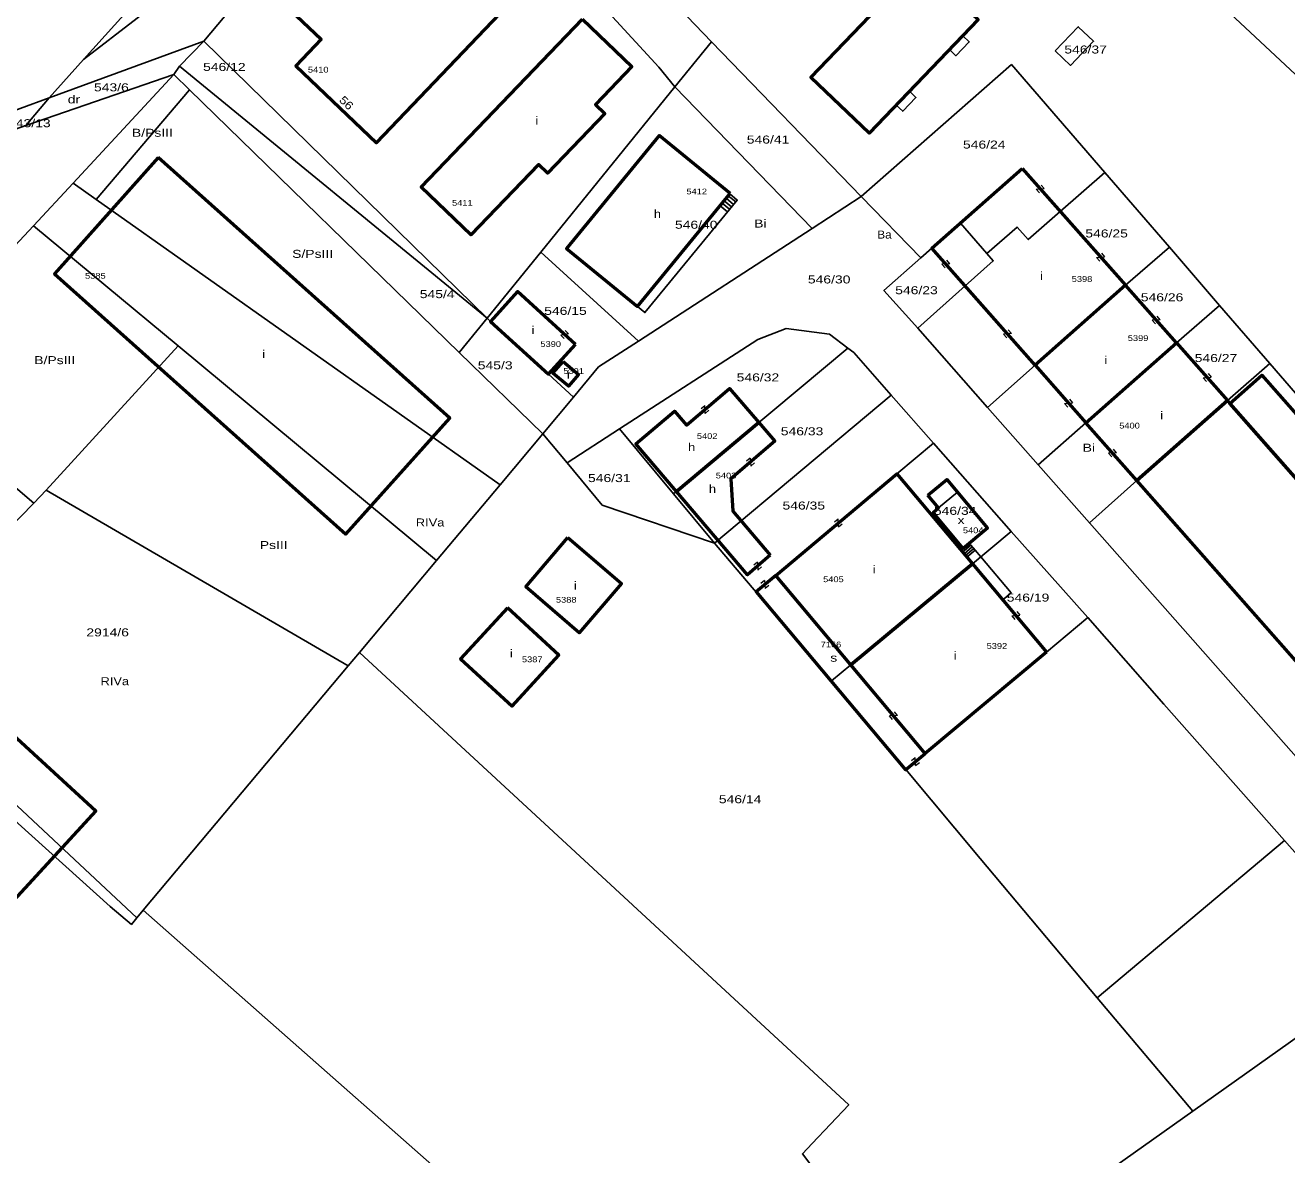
# Model space of a CAD drawing. Extents: x 4641351 to 4644672, y 5357112 to 5362385.
# Drawn here: x 4642962.5 to 4643159.5, y 5360710 to 5360886.4 of the extents above; entities that cross this region are included whole.
import ezdxf
from ezdxf.enums import TextEntityAlignment as Align

# ---------------------------------------------------------------- set-up
doc = ezdxf.new("R2010")
doc.units = 0
doc.header["$LTSCALE"] = 0.5
for name, color, linetype in [('1', 7, 'Continuous'), ('24', 7, 'Continuous'), ('26', 7, 'Continuous'), ('4', 7, 'Continuous')]:
    doc.layers.add(name, color=color, linetype=linetype)
for name, color, linetype, lineweight in [('15', 7, 'Continuous', 25), ('16', 7, 'Continuous', 25), ('25', 7, 'Continuous', 25), ('27', 7, 'Continuous', 25), ('3', 7, 'Continuous', 13), ('6', 7, 'Continuous', 25)]:
    doc.layers.add(name, color=color, linetype=linetype, lineweight=lineweight)

msp = doc.modelspace()

# ---------------------------------------------------------------- linework, layer by layer
at = {"layer": '15'}
for p, q in [((4643072.817, 5360858.076), (4643071.657, 5360859.028)), ((4643073.134, 5360858.463), (4643071.974, 5360859.415)), ((4643073.451, 5360858.849), (4643072.291, 5360859.801)), ((4643072.183, 5360857.303), (4643071.023, 5360858.255)), ((4643072.5, 5360857.69), (4643071.34, 5360858.642)), ((4643110.632, 5360804.726), (4643109.335, 5360803.637))]:
    msp.add_line(p, q, dxfattribs=at)
for points in [[(4643058.105, 5360842.516), (4643059.265, 5360841.564), (4643073.69, 5360859.14), (4643072.53, 5360860.092)], [(4643109.555, 5360803.376), (4643110.851, 5360804.465), (4643110.191, 5360805.251), (4643108.894, 5360804.162)], [(4643110.421, 5360802.344), (4643111.718, 5360803.433), (4643110.852, 5360804.465), (4643109.555, 5360803.376)], [(4643110.421, 5360802.344), (4643111.718, 5360803.433), (4643116.455, 5360797.792), (4643115.158, 5360796.703)]]:
    msp.add_lwpolyline(points, close=True, dxfattribs=at)
msp.add_lwpolyline([(4643110.411, 5360804.989), (4643110.412, 5360804.989), (4643109.115, 5360803.899)], dxfattribs=at)
at = {"layer": '16'}
for points in [[(4643108.909, 5360884.807), (4643109.919, 5360883.838), (4643107.842, 5360881.673), (4643106.832, 5360882.642)], [(4643100.601, 5360876.148), (4643101.611, 5360875.179), (4643099.534, 5360873.014), (4643098.524, 5360873.983)]]:
    msp.add_lwpolyline(points, close=True, dxfattribs=at)
at = {"layer": '25'}
for p, q in [((4643034.618, 5360840.702), (4642990.368, 5360883.956)), ((4642962.597, 5360870.762), (4642966.205, 5360875.094)), ((4643063.761, 5360813.259), (4643090.967, 5360836.02)), ((4643070.16, 5360805.568), (4643097.742, 5360828.664)), ((4643116.466, 5360807.362), (4643110.421, 5360802.344))]:
    msp.add_line(p, q, dxfattribs=at)
for points in [[(4643069.651, 5360883.835), (4643093.07, 5360859.707), (4643116.529, 5360880.298), (4643131.101, 5360863.442), (4643141.186, 5360851.776), (4643149.036, 5360842.696), (4643156.868, 5360833.637), (4643184.618, 5360801.537), (4643214.585, 5360827.069), (4643236.635, 5360845.843), (4643221.786, 5360867.068), (4643195.021, 5360847.847), (4643169.275, 5360871.091), (4643163.235, 5360876.545), (4643124.137, 5360913.093), (4643100.704, 5360935.255)], [(4643063.945, 5360876.814), (4643069.651, 5360883.835), (4643059.534, 5360894.45), (4643037.963, 5360917.65), (4643027.414, 5360926.568)], [(4643034.618, 5360840.702), (4643043.005, 5360850.99), (4643063.945, 5360876.814), (4643061.441, 5360879.907), (4643045.808, 5360896.938), (4643031.568, 5360910.853), (4643023.758, 5360919.579), (4643022.322, 5360920.713), (4643011.407, 5360909.06)], [(4642961.719, 5360873.449), (4642966.205, 5360875.094), (4642971.614, 5360881.095), (4643003.059, 5360915.975), (4642999.77, 5360918.699), (4642994.247, 5360913.207), (4642984.526, 5360904.064), (4642964.268, 5360890.656), (4642955.311, 5360884.878), (4642930.858, 5360865.649), (4642926.797, 5360863.336), (4642922.443, 5360859.045)], [(4642990.368, 5360883.956), (4643011.407, 5360909.06), (4643008.564, 5360911.382), (4642996.718, 5360900.487), (4642971.614, 5360881.095)], [(4642985.672, 5360878.737), (4642986.592, 5360880.024), (4642990.368, 5360883.956), (4642966.205, 5360875.094)], [(4642938.39, 5360782.43), (4642958.734, 5360764.143), (4642975.77, 5360748.826), (4642979.077, 5360746.004), (4642979.936, 5360747.03), (4642980.927, 5360748.211), (4643012.937, 5360786.377), (4643014.684, 5360788.461), (4643026.742, 5360802.84), (4643036.653, 5360814.656), (4643043.329, 5360822.616), (4643030.257, 5360835.336), (4642988.127, 5360876.348), (4642985.672, 5360878.737), (4642962.597, 5360870.762), (4642955.59, 5360868.34)], [(4643030.257, 5360835.336), (4643034.618, 5360840.702), (4642986.592, 5360880.024)], [(4643058.255, 5360837.085), (4643085.39, 5360854.71), (4643063.945, 5360876.814)], [(4643102.381, 5360850.115), (4643104.096, 5360851.629), (4643108.549, 5360855.545), (4643112.686, 5360850.769), (4643117.404, 5360854.928), (4643119.153, 5360852.966), (4643124.131, 5360857.366), (4643131.101, 5360863.442)], [(4643266.424, 5360802.366), (4643263.866, 5360805.827), (4643261.783, 5360808.646), (4643211.704, 5360773.753), (4643179.474, 5360751.053), (4643160.966, 5360772.173), (4643128.7, 5360808.727), (4643120.697, 5360817.766), (4643112.778, 5360826.718), (4643101.889, 5360839.154), (4643096.614, 5360845.019), (4643102.381, 5360850.115), (4643093.07, 5360859.707), (4643085.39, 5360854.71)], [(4643048.115, 5360828.339), (4643052.03, 5360833.076), (4643058.255, 5360837.085), (4643043.005, 5360850.99)], [(4643112.778, 5360826.718), (4643120.209, 5360833.366), (4643134.344, 5360845.823), (4643141.186, 5360851.776)], [(4643101.889, 5360839.154), (4643109.272, 5360845.76), (4643113.681, 5360849.637), (4643112.686, 5360850.769)], [(4643120.697, 5360817.766), (4643128.14, 5360824.365), (4643142.316, 5360836.823), (4643149.036, 5360842.696)], [(4643043.329, 5360822.616), (4643048.115, 5360828.339), (4643044.22, 5360831.937), (4643035.158, 5360840.193), (4643034.618, 5360840.702)], [(4643047.11, 5360818.093), (4643055.325, 5360823.391), (4643076.936, 5360837.335), (4643081.35, 5360839.071), (4643088.079, 5360838.197), (4643090.967, 5360836.02), (4643091.885, 5360835.326), (4643097.742, 5360828.664), (4643104.333, 5360821.16), (4643116.466, 5360807.362), (4643128.426, 5360793.918), (4643140.298, 5360780.41), (4643159.153, 5360759.103), (4643176.605, 5360739.362)], [(4643128.7, 5360808.727), (4643136.081, 5360815.364), (4643150.266, 5360827.843), (4643156.868, 5360833.637)], [(4643070.16, 5360805.568), (4643063.761, 5360813.259), (4643055.325, 5360823.391)], [(4643144.866, 5360716.862), (4643129.888, 5360734.54), (4643111.615, 5360756.3), (4643100.008, 5360770.188), (4643088.402, 5360784.067), (4643070.16, 5360805.568), (4643052.614, 5360811.507), (4643047.11, 5360818.093), (4643043.329, 5360822.616)], [(4643088.402, 5360784.067), (4643091.416, 5360786.569), (4643110.421, 5360802.344), (4643098.619, 5360816.381), (4643104.333, 5360821.16)], [(4643266.424, 5360802.366), (4643241.486, 5360784.406), (4643211.598, 5360763.109), (4643176.605, 5360739.362), (4643144.866, 5360716.862), (4643103.076, 5360687.21), (4643043.425, 5360643.495), (4642978.815, 5360596.146), (4642952.32, 5360560.117), (4642913.168, 5360505.182), (4642909.005, 5360494.861), (4642897.054, 5360474.757), (4642897.62, 5360474.44), (4642886.991, 5360460.422)], [(4643100.008, 5360770.188), (4643103.043, 5360772.722), (4643122.002, 5360788.553), (4643128.426, 5360793.918)], [(4643014.684, 5360788.461), (4643091.115, 5360717.855), (4643085.385, 5360711.775), (4643083.869, 5360710.166), (4643093.53, 5360697.488), (4643094.895, 5360698.515), (4643103.076, 5360687.21)]]:
    msp.add_lwpolyline(points, dxfattribs=at)
msp.add_lwpolyline([(4643123.339, 5360882.419), (4643125.76, 5360880.164), (4643129.362, 5360883.939), (4643126.962, 5360886.195)], close=True, dxfattribs=at)
at = {"layer": '27'}
for points in [[(4642966.205, 5360875.094), (4642971.614, 5360881.095), (4642996.718, 5360900.487), (4643008.564, 5360911.382), (4643022.156, 5360923.888), (4643059.701, 5360971.966), (4643061.134, 5360973.801), (4643117.007, 5361026.845), (4643161.963, 5361072.833), (4643185.093, 5361090.619), (4643211.568, 5361122.216), (4643225.268, 5361138.578), (4643232.759, 5361147.52), (4643257.532, 5361174.087)], [(4643266.424, 5360802.366), (4643263.866, 5360805.827), (4643261.783, 5360808.646), (4643312.049, 5360844.358), (4643348.449, 5360870.219), (4643347.38, 5360871.06), (4643328.35, 5360886.006), (4643322.35, 5360889.651), (4643295.026, 5360869.061), (4643271.24, 5360903.578), (4643227.458, 5360871.385), (4643221.786, 5360867.068), (4643195.021, 5360847.847), (4643169.275, 5360871.091), (4643163.235, 5360876.545), (4643124.137, 5360913.093), (4643100.704, 5360935.255), (4643074.641, 5360909.408), (4643059.534, 5360894.45), (4643037.963, 5360917.65), (4643027.414, 5360926.568), (4643022.322, 5360920.713), (4643011.407, 5360909.06)], [(4642990.368, 5360883.956), (4643011.407, 5360909.06), (4643008.564, 5360911.382)], [(4643404.058, 5360902.512), (4643353.914, 5360865.927), (4643316.19, 5360838.578), (4643266.424, 5360802.366), (4643241.486, 5360784.406), (4643211.598, 5360763.109), (4643176.605, 5360739.362), (4643144.866, 5360716.862), (4643103.076, 5360687.21)], [(4642954.708, 5360868.034), (4642955.59, 5360868.34), (4642962.597, 5360870.762), (4642985.672, 5360878.737), (4642986.592, 5360880.024), (4642990.368, 5360883.956), (4642966.205, 5360875.094), (4642961.719, 5360873.449), (4642922.443, 5360859.045), (4642913.439, 5360855.743), (4642908.738, 5360853.709), (4642885.535, 5360844.16), (4642866.506, 5360838.934), (4642864.482, 5360838.514)], [(4642934.508, 5360821.537), (4642935.707, 5360823.178), (4642950.956, 5360840.529), (4642958.74, 5360849.687), (4642963.785, 5360855.129), (4642969.95, 5360861.779), (4642985.672, 5360878.737)], [(4642973.575, 5360859.218), (4642988.127, 5360876.348), (4642985.672, 5360878.737)], [(4643036.653, 5360814.656), (4643043.329, 5360822.616), (4643048.115, 5360828.339), (4643044.22, 5360831.937), (4643035.158, 5360840.193), (4643034.618, 5360840.702), (4642986.592, 5360880.024)], [(4642986.394, 5360836.351), (4643026.742, 5360802.84), (4643036.653, 5360814.656), (4642973.575, 5360859.218), (4642969.95, 5360861.779)], [(4642963.816, 5360811.825), (4642965.756, 5360813.808), (4642986.394, 5360836.351), (4642963.785, 5360855.129)], [(4642864.42, 5360741.249), (4642904.695, 5360730.14), (4642905.897, 5360734.858), (4642909.222, 5360743.582), (4642913.126, 5360751.433), (4642918.085, 5360758.796), (4642921.09, 5360764.54), (4642924.397, 5360770.846), (4642935.125, 5360788.291), (4642938.4, 5360785.837), (4642963.816, 5360811.825), (4642951.631, 5360822.167), (4642943.532, 5360813.297), (4642934.508, 5360821.537), (4642929.655, 5360814.892), (4642921.095, 5360803.173), (4642915.206, 5360790.475), (4642892.458, 5360790.663)], [(4642938.4, 5360785.837), (4642979.936, 5360747.03), (4642980.927, 5360748.211), (4643012.937, 5360786.377), (4642965.756, 5360813.808)], [(4643012.937, 5360786.377), (4643014.684, 5360788.461), (4643026.742, 5360802.84)], [(4642980.927, 5360748.211), (4643026.009, 5360708.462), (4643056.068, 5360680.661), (4643062.834, 5360674.403)]]:
    msp.add_lwpolyline(points, dxfattribs=at)
for points in [[(4643043.005, 5360850.99), (4643058.255, 5360837.085), (4643085.39, 5360854.71), (4643063.945, 5360876.814)], [(4643112.778, 5360826.718), (4643120.697, 5360817.766), (4643128.7, 5360808.727), (4643136.081, 5360815.364), (4643150.266, 5360827.843), (4643156.868, 5360833.637), (4643149.036, 5360842.696), (4643141.186, 5360851.776), (4643134.344, 5360845.823), (4643120.209, 5360833.366)], [(4643100.008, 5360770.188), (4643111.615, 5360756.3), (4643129.888, 5360734.54), (4643159.153, 5360759.103), (4643140.298, 5360780.41), (4643128.426, 5360793.918), (4643122.002, 5360788.553), (4643103.043, 5360772.722)]]:
    msp.add_lwpolyline(points, close=True, dxfattribs=at)
at = {"layer": '3'}
for p, q in [((4643120.402, 5360860.817), (4643121.648, 5360860.919)), ((4643121.151, 5360861.48), (4643121.648, 5360860.919)), ((4643120.402, 5360860.817), (4643120.899, 5360860.256)), ((4643106.905, 5360849.201), (4643105.659, 5360849.101)), ((4643106.155, 5360848.539), (4643105.659, 5360849.101)), ((4643106.905, 5360849.201), (4643106.409, 5360849.763)), ((4643129.819, 5360850.18), (4643131.065, 5360850.282)), ((4643129.819, 5360850.18), (4643130.316, 5360849.619)), ((4643130.568, 5360850.843), (4643131.065, 5360850.282)), ((4643139.765, 5360840.457), (4643138.519, 5360840.355)), ((4643139.016, 5360839.794), (4643138.519, 5360840.355)), ((4643139.765, 5360840.457), (4643139.268, 5360841.018)), ((4643047.36, 5360838.248), (4643046.132, 5360838.014)), ((4643046.686, 5360837.509), (4643046.132, 5360838.014)), ((4643047.36, 5360838.248), (4643046.806, 5360838.753)), ((4643116.527, 5360838.296), (4643115.281, 5360838.196)), ((4643115.777, 5360837.634), (4643115.281, 5360838.196)), ((4643116.527, 5360838.296), (4643116.031, 5360838.858)), ((4643146.478, 5360831.367), (4643147.724, 5360831.469)), ((4643146.478, 5360831.367), (4643146.975, 5360830.806)), ((4643147.227, 5360832.03), (4643147.724, 5360831.469)), ((4643124.827, 5360827.369), (4643126.073, 5360827.467)), ((4643124.827, 5360827.369), (4643125.323, 5360826.806)), ((4643125.577, 5360828.03), (4643126.073, 5360827.467)), ((4643068.04, 5360826.579), (4643068.611, 5360827.066)), ((4643068.689, 5360825.818), (4643068.611, 5360827.066)), ((4643068.689, 5360825.818), (4643069.26, 5360826.305)), ((4643132.935, 5360819.686), (4643131.689, 5360819.586)), ((4643132.185, 5360819.024), (4643131.689, 5360819.586)), ((4643132.935, 5360819.686), (4643132.439, 5360820.248)), ((4643075.716, 5360818.852), (4643075.145, 5360818.365)), ((4643075.716, 5360818.852), (4643075.794, 5360817.604)), ((4643076.365, 5360818.091), (4643075.794, 5360817.604)), ((4643088.883, 5360808.873), (4643089.458, 5360809.355)), ((4643089.526, 5360808.107), (4643089.458, 5360809.355)), ((4643089.526, 5360808.107), (4643090.101, 5360808.589)), ((4643076.835, 5360802.607), (4643076.264, 5360802.12)), ((4643076.835, 5360802.607), (4643076.913, 5360801.359)), ((4643077.484, 5360801.846), (4643076.913, 5360801.359)), ((4643077.975, 5360799.712), (4643077.4, 5360799.23)), ((4643077.975, 5360799.712), (4643078.043, 5360798.464)), ((4643078.618, 5360798.946), (4643078.043, 5360798.464)), ((4643116.586, 5360794.226), (4643117.834, 5360794.294)), ((4643116.586, 5360794.226), (4643117.068, 5360793.651)), ((4643117.352, 5360794.869), (4643117.834, 5360794.294)), ((4643098.715, 5360778.654), (4643097.467, 5360778.586)), ((4643097.949, 5360778.011), (4643097.467, 5360778.586)), ((4643098.715, 5360778.654), (4643098.233, 5360779.229)), ((4643100.918, 5360771.591), (4643101.493, 5360772.073)), ((4643101.561, 5360770.825), (4643101.493, 5360772.073)), ((4643101.561, 5360770.825), (4643102.136, 5360771.307))]:
    msp.add_line(p, q, dxfattribs=at)
at = {"layer": '3', "lineweight": 53}
for points in [[(4643052.673, 5360909.528), (4643072.978, 5360930.694), (4643077.36, 5360926.49), (4643085.149, 5360934.609), (4643120.306, 5360900.881), (4643112.366, 5360892.604), (4643111.503, 5360893.432), (4643108.374, 5360890.171), (4643111.332, 5360887.333), (4643094.301, 5360869.581), (4643085.212, 5360878.301), (4643102.284, 5360896.095), (4643104.51, 5360893.971), (4643107.56, 5360897.15), (4643088.413, 5360915.522), (4643085.269, 5360912.245), (4643087.448, 5360910.154), (4643070.464, 5360892.455)], [(4643001.02, 5360891.62), (4643008.725, 5360884.255), (4643004.771, 5360880.119), (4643017.344, 5360868.101), (4643038.875, 5360890.625), (4643031.17, 5360897.99), (4643035.486, 5360902.505), (4643022.914, 5360914.523)], [(4643049.5, 5360887.38), (4643057.228, 5360879.972), (4643051.55, 5360874.05), (4643053.009, 5360872.651), (4643044.07, 5360863.329), (4643042.638, 5360864.702), (4643032.1, 5360853.71), (4643024.346, 5360861.144)], [(4643072.57, 5360860.14), (4643061.515, 5360869.214), (4643047.05, 5360851.59), (4643058.105, 5360842.516)], [(4642983.276, 5360865.788), (4642967.044, 5360847.642), (4643012.554, 5360806.933), (4643028.786, 5360825.079)], [(4643118.213, 5360864.045), (4643134.344, 5360845.823), (4643120.209, 5360833.366), (4643104.096, 5360851.629)], [(4643134.344, 5360845.823), (4643120.209, 5360833.366), (4643128.14, 5360824.365), (4643142.316, 5360836.823)], [(4643048.449, 5360836.579), (4643039.388, 5360844.835), (4643035.158, 5360840.193), (4643044.22, 5360831.937)], [(4643142.316, 5360836.823), (4643150.266, 5360827.843), (4643136.081, 5360815.364), (4643128.14, 5360824.365)], [(4643046.502, 5360833.948), (4643048.916, 5360831.872), (4643047.358, 5360830.061), (4643044.914, 5360832.102)], [(4643150.65, 5360827.389), (4643155.645, 5360831.786), (4643187.364, 5360795.76), (4643184.512, 5360793.249), (4643180.698, 5360797.582), (4643178.552, 5360795.693)], [(4643064.194, 5360813.621), (4643057.859, 5360821.055), (4643063.887, 5360826.192), (4643065.768, 5360823.985), (4643072.503, 5360829.727), (4643077.059, 5360824.384)], [(4643136.081, 5360815.364), (4643150.266, 5360827.843), (4643150.65, 5360827.389), (4643178.552, 5360795.693), (4643180.698, 5360797.582), (4643184.512, 5360793.249), (4643182.154, 5360791.174), (4643168.224, 5360778.914), (4643164.361, 5360783.293)], [(4643078.851, 5360803.667), (4643075.274, 5360800.619), (4643064.194, 5360813.621), (4643077.059, 5360824.384), (4643079.549, 5360821.463), (4643072.7, 5360815.624), (4643072.981, 5360810.555)], [(4643110.421, 5360802.344), (4643091.416, 5360786.569), (4643079.706, 5360800.513), (4643098.62, 5360816.396)], [(4643103.483, 5360813.047), (4643106.433, 5360815.498), (4643112.765, 5360807.877), (4643108.978, 5360804.731), (4643104.296, 5360810.366), (4643105.132, 5360811.061)], [(4642910.437, 5360788.826), (4642926.819, 5360806.649), (4642973.492, 5360763.749), (4642957.11, 5360745.926)], [(4643047.239, 5360806.417), (4643055.602, 5360799.228), (4643049.012, 5360791.562), (4643040.649, 5360798.751)], [(4643122.002, 5360788.553), (4643103.043, 5360772.722), (4643091.416, 5360786.569), (4643110.421, 5360802.344)], [(4643079.706, 5360800.513), (4643076.643, 5360797.941), (4643099.979, 5360770.149), (4643103.043, 5360772.722)], [(4643037.807, 5360795.445), (4643030.487, 5360787.501), (4643038.519, 5360780.1), (4643045.839, 5360788.044)]]:
    msp.add_lwpolyline(points, close=True, dxfattribs=at)
at = {"layer": '6'}
msp.add_line((4643108.083, 5360813.512), (4643105.132, 5360811.061), dxfattribs=at)

# ---------------------------------------------------------------- texts
at = {"layer": '1', "width": 1.2}
msp.add_text('56', height=1.25, rotation=316.29, dxfattribs=at).set_placement((4643012.221, 5360873.862), align=Align.CENTER)
at = {"layer": '24', "width": 1.3}
for s, p in [('546/37', (4643124.781, 5360882.026)), ('546/12', (4642990.263, 5360879.302)), ('543/6', (4642973.224, 5360876.118)), ('543/13', (4642959.811, 5360870.519)), ('546/41', (4643075.183, 5360867.96)), ('546/24', (4643108.95, 5360867.181)), ('546/40', (4643063.964, 5360854.657)), ('546/25', (4643128.06, 5360853.299)), ('546/30', (4643084.727, 5360846.114)), ('545/4', (4643024.108, 5360843.823)), ('546/23', (4643098.367, 5360844.43)), ('546/26', (4643136.723, 5360843.328)), ('546/15', (4643043.543, 5360841.205)), ('545/3', (4643033.168, 5360832.706)), ('546/27', (4643145.142, 5360833.84)), ('546/32', (4643073.6, 5360830.819)), ('546/33', (4643080.495, 5360822.4)), ('546/31', (4643050.383, 5360815.092)), ('546/35', (4643080.766, 5360810.802)), ('546/34', (4643104.41, 5360809.977)), ('546/19', (4643115.789, 5360796.427)), ('2914/6', (4642972.036, 5360790.995)), ('546/14', (4643070.822, 5360764.935))]:
    msp.add_text(s, height=1.25, dxfattribs=at).set_placement(p)
at = {"layer": '26'}
for s, width, p in [('dr', 1.3, (4642969.123, 5360874.234)), ('B/PsIII', 1.3, (4642979.156, 5360869.023)), ('Bi', 1.3, (4643076.34, 5360854.844)), ('Ba', 1.1, (4643095.572, 5360853.123)), ('S/PsIII', 1.3, (4643004.179, 5360850.113)), ('B/PsIII', 1.3, (4642963.898, 5360833.51)), ('Bi', 1.3, (4643127.644, 5360819.837)), ('RIVa', 1.2, (4643023.495, 5360808.159)), ('PsIII', 1.3, (4642999.122, 5360804.635)), ('RIVa', 1.2, (4642974.249, 5360783.371))]:
    msp.add_text(s, height=1.25, dxfattribs=dict(at, width=width)).set_placement(p)
at = {"layer": '4', "width": 1.2}
for s, p in [('5410', (4643006.635, 5360879.052)), ('5412', (4643065.763, 5360860.03)), ('5411', (4643029.154, 5360858.246)), ('5385', (4642971.834, 5360846.852)), ('5398', (4643125.936, 5360846.356)), ('5399', (4643134.691, 5360837.125)), ('5390', (4643042.954, 5360836.198)), ('5391', (4643046.541, 5360831.985)), ('5400', (4643133.359, 5360823.46)), ('5402', (4643067.387, 5360821.822)), ('5403', (4643070.341, 5360815.662)), ('5404', (4643108.938, 5360807.109)), ('5405', (4643087.108, 5360799.463)), ('5388', (4643045.378, 5360796.259)), ('7166', (4643086.729, 5360789.278)), ('5392', (4643112.645, 5360789.045)), ('5387', (4643040.067, 5360786.957))]:
    msp.add_text(s, height=0.9, dxfattribs=at).set_placement(p)
at = {"layer": '4'}
for s, width, p in [('i', 1.3, (4643042.387, 5360870.934)), ('h', 1.2, (4643061.227, 5360856.352)), ('i', 1.3, (4643121.214, 5360846.673)), ('i', 1.3, (4643041.786, 5360838.197)), ('i', 1.3, (4642999.712, 5360834.471)), ('i', 1.3, (4643131.266, 5360833.509)), ('i', 1.3, (4643047.321, 5360831.249)), ('i', 1.3, (4643139.968, 5360824.896)), ('h', 1.2, (4643066.573, 5360819.925)), ('h', 1.2, (4643069.824, 5360813.412)), ('x', 1.3, (4643108.655, 5360808.539)), ('i', 1.3, (4643095.083, 5360800.841)), ('i', 1.3, (4643048.393, 5360798.312)), ('i', 1.3, (4643038.403, 5360787.722)), ('s', 1.3, (4643088.767, 5360787.034)), ('i', 1.3, (4643107.736, 5360787.373))]:
    msp.add_text(s, height=1.25, dxfattribs=dict(at, width=width)).set_placement(p, align=Align.CENTER)

doc.saveas('drawing.dxf')
